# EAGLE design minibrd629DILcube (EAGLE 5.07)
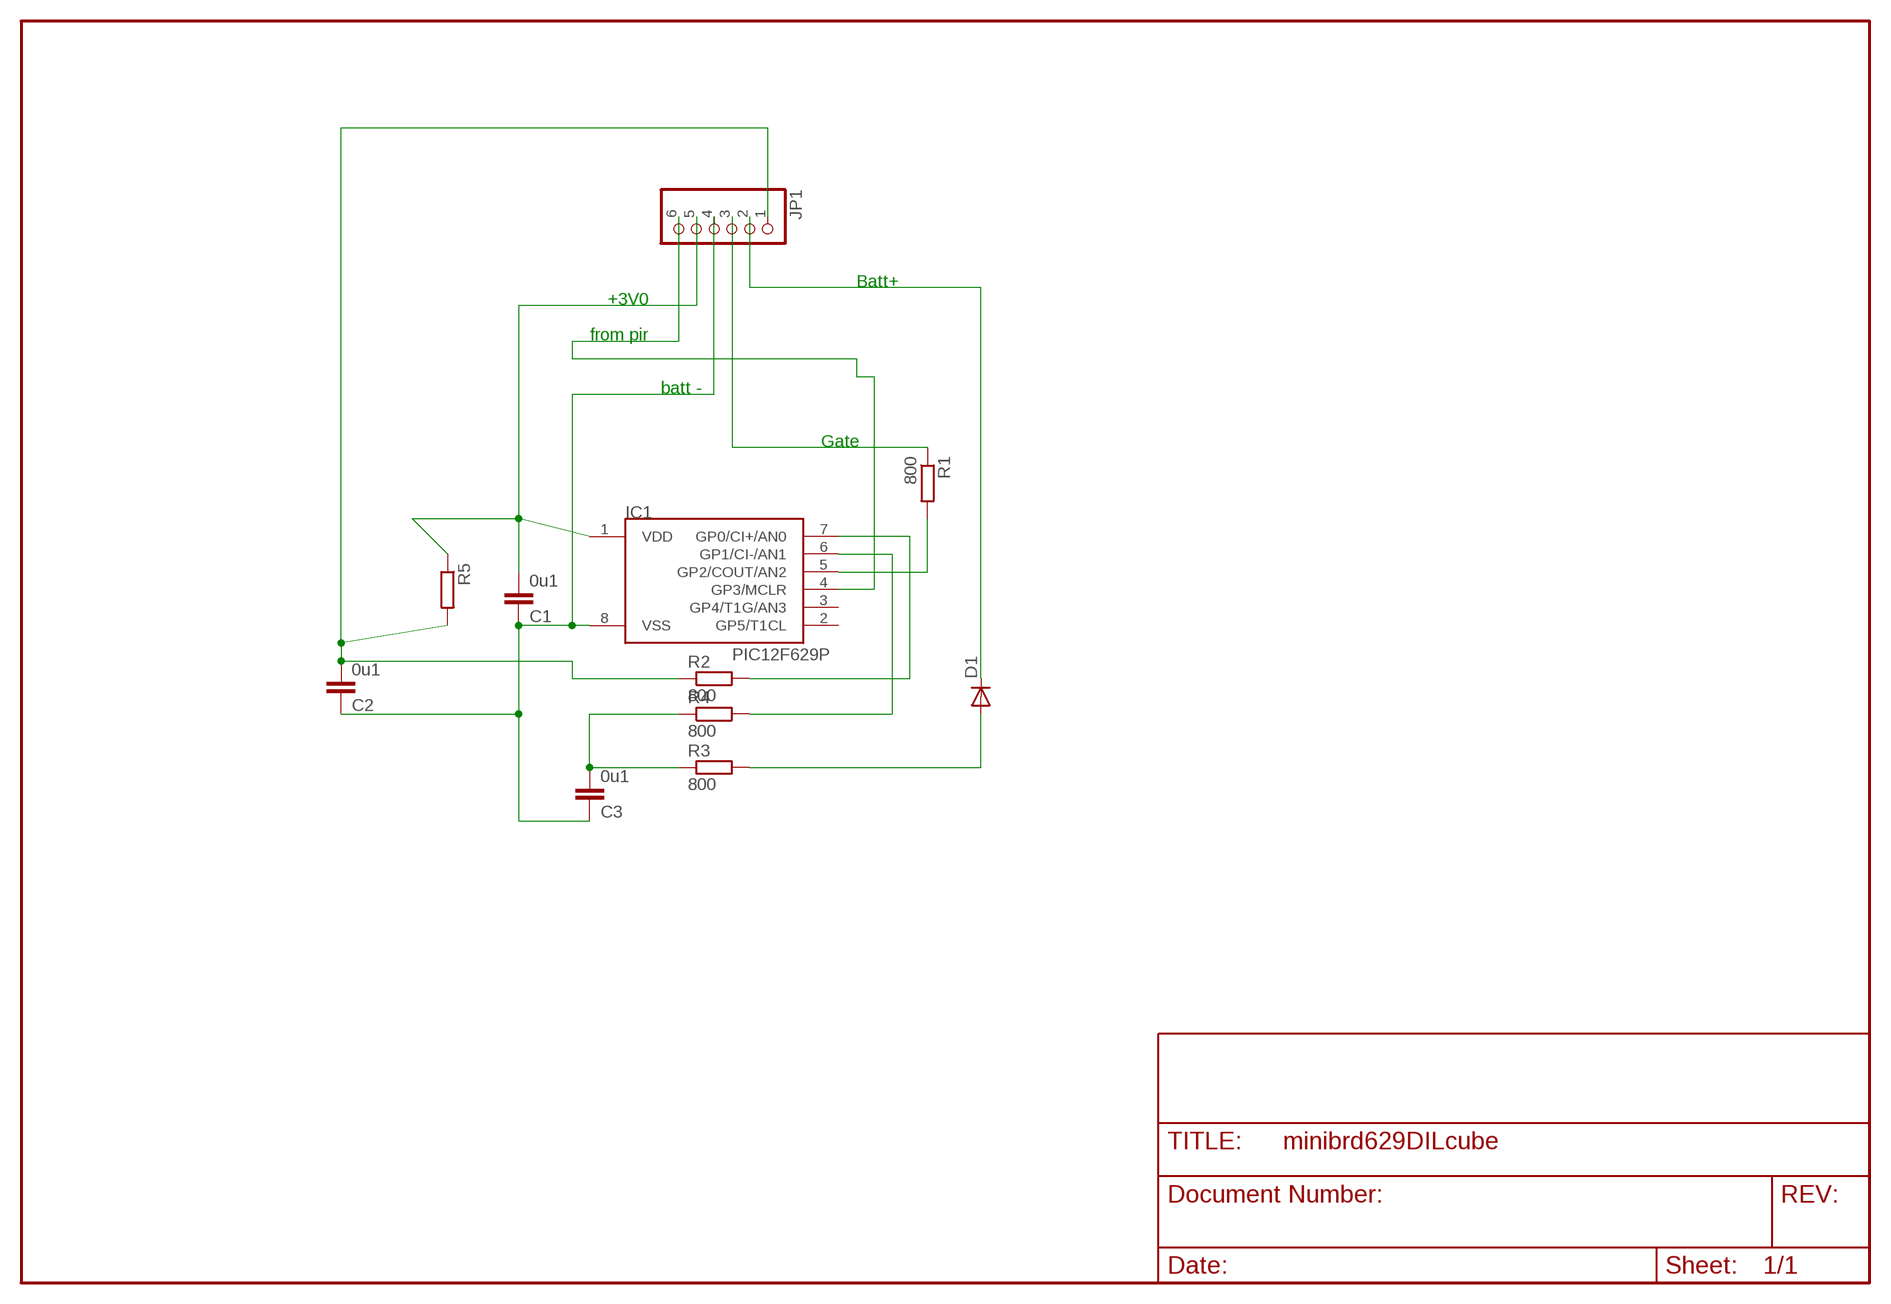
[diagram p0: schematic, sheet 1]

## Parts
C1  0u1  C-EUC1206  [C1206]
C2  0u1  C-EUC1206  [C1206]
C3  0u1  C-EUC1206  [C1206]
D1  DIODE-MINIMELF  [MINIMELF]
IC1  PIC12F629P  [DIL8]
JP1  PINHD-1X6  [1X06BOX]
R1  800  R-EU_R1206  [R1206]
R2  800  R-EU_R1206  [R1206]
R3  800  R-EU_R1206  [R1206]
R4  800  R-EU_R1206  [R1206]
R5  R-EU_0613/5V  [P0613V]

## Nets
GATE: JP1.3 R1.1
N$1: IC1.5(GP2/COUT/AN2) R1.2
N$4: IC1.7(GP0/CI+/AN0) R2.2
N$7: C3.2 R3.1 R4.1
N$8: IC1.6(GP1/CI-/AN1) R4.2
N$9: C2.2 JP1.1 R2.1 R5.2
N$10: D1.A R3.2
PIR: IC1.4(GP3/MCLR) JP1.6
V3: C1.2 IC1.1(VDD) JP1.5 R5.1
V+: D1.C JP1.2
V-: C1.1 C2.1 C3.1 IC1.8(VSS) JP1.4
Unconnected: IC1.2(GP5/T1CL) IC1.3(GP4/T1G/AN3)

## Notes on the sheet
- Batt+
- +3V0
- from pir
- batt -
- Gate

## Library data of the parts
C1-C3 = rcl:C-EU: CAPACITOR, European symbol
D1 = diode-1:DIODE-: DIODE
IC1 = microchip-3:PIC12F6*: uPC nW 1k Program Flash memory 2x Timer Comparator 10b A/D converter/ 4xIN
JP1 = pinhead:PINHD-1X6: PIN HEADER
R1-R5 = rcl:R-EU_: RESISTOR, European symbol

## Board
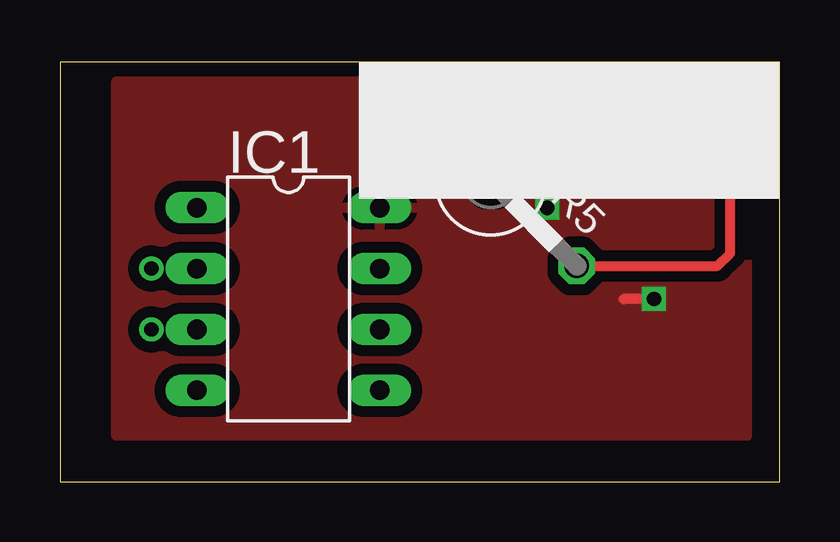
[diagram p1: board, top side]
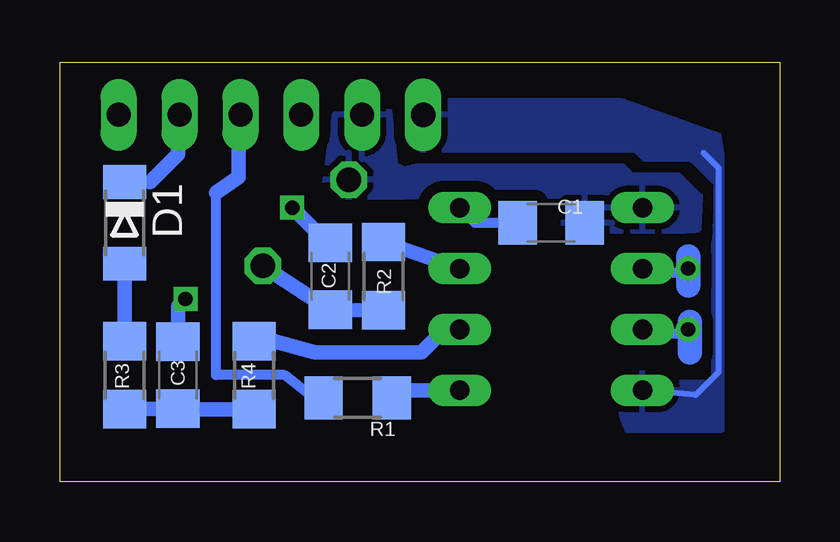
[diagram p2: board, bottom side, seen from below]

Size 30 x 17.5 mm. Coordinates in mm from the lower left corner, seen from the top.
Outline: 0,0 30,0 30,17.5 0,17.5 0,0
Copper layers (1*16): Top 0.035mm / dielectric 1.5mm / Bottom 0.035mm
Design rules "default *": minimum track width 10mil, minimum drill 24mil, track to track 18mil, track to pad 12mil, pad to pad 8mil, via to via 8mil, smd to smd 8mil, copper to edge 1mil, drill to drill 8mil, minimum pad ring 10mil, minimum via ring 8mil, stop-mask expansion 4mil, vias tented up to drill 0mil, thermal gap 10mil

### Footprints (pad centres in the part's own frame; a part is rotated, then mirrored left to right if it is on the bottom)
C1206 = smd 1.6 x 1.8: 1 -1.4,0; 2 1.4,0
MINIMELF = smd 1.4 x 1.8: A 1.7,0; C -1.7,0
DIL8 = drill 0.813 long: 1 -3.81,-3.81; 2 -1.27,-3.81; 3 1.27,-3.81; 4 3.81,-3.81; 5 3.81,3.81; 6 1.27,3.81; 7 -1.27,3.81; 8 -3.81,3.81
1X06BOX = drill 1 long: 1 -6.35,0; 2 -3.81,0; 3 -1.27,0; 4 1.27,0; 5 3.81,0 | drill 1.016 long: 6 6.35,0
R1206 = smd 1.6 x 1.803: 1 -1.422,0; 2 1.422,0
P0613V = drill 1.016 octagon: 1 -2.54,0; 2 2.54,0

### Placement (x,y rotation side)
C1  9.53,10.79 0 bottom
C2  18.73,8.57 270 bottom
C3  25.08,4.45 270 bottom
D1  27.3,10.79 270 bottom
IC1  9.53,7.62 270 top
JP1  21.21,15.3 180 top
R1  17.59,3.49 0 bottom
R2  16.51,8.57 90 bottom
R3  27.3,4.45 90 bottom
R4  21.91,4.45 90 bottom
R5  19.75,10.79 315 top

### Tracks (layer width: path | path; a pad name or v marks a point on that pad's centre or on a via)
GATE
  Bottom 0.406: R1.1 19.05,3.17 20.64,4.45 23.5,4.45 23.5,12.06 | 22.54,15.05 JP1.3
  Bottom 0.61: 23.5,12.06 22.54,12.7 22.54,15.05
N$1
  Bottom 0.406: 15.56,3.81 R1.2
  Bottom 0.61: IC1.5 15.56,3.81
N$2  (via drill 0.6)
  other vias: 3.81,6.35
N$3  (via drill 0.6)
  other vias: 3.81,8.89
N$4
  Bottom 0.61: IC1.7 R2.2
N$5
  Bottom 0.406: 5.78,6.16 3.75,6.16 3.75,6.29
  Bottom 1.016: 3.75,5.4 3.75,6.29 3.75,6.67
N$6
  Bottom 0.406: 5.71,8.76 5.71,8.7 3.81,8.7 3.81,8.64
  Bottom 1.016: 3.81,8.19 3.81,8.64 3.81,9.4
N$7
  Bottom 0.406: 25.06,3.02 C3.2 | 27.28,3.04 R3.1
  Bottom 0.61: R4.1 25.06,3.02 | C3.2 27.28,3.04
N$8
  Bottom 0.406: 21.11,5.87 R4.2 | IC1.6 13.97,6.35
  Bottom 0.61: 21.11,5.87 19.37,5.4 14.92,5.4 13.97,6.35
N$9
  Top 0.406: R5.2 27.41,9 27.94,9.53 27.94,14.92 JP1.1
  Bottom 0.61: R2.1 C2.2 R5.2
N$10
  Bottom 0.61: R3.2 D1.A
PIR
  Bottom 0.254: IC1.4 3.49,3.62 2.54,4.57 2.54,13.08 3.17,13.72
  pour Bottom (isolate 0.406, rank 2): 4.25,4.51 6.03,4.51 6.6,3.94 6.6,2.79 6.35,2.16 2.41,2.16 2.41,13.65 2.54,14.41 6.6,15.88 15.49,15.88 15.56,13.91 14.16,13.65 9.4,13.4 4.32,13.4 2.73,12.19 2.73,4.25 2.98,4.13 4.25,4.13 4.45,4.32
V3
  pour Bottom (isolate 0.406): 3.62,10.48 3.37,10.54 3.3,11.87 4.19,12.76 6.16,12.76 6.54,13.14 15.11,13.14 15.62,13.02 16,13.21 16.26,15.43 18.54,15.3 19.05,11.87 9.02,11.94 9.02,10.48
V+
  Bottom 0.406: D1.C 26.24,12.49 | 25.08,15.24 JP1.2
  Bottom 0.61: 26.24,12.49 25.08,13.65 25.08,15.24
V-  (via drill 0.6)
  Top 0.406: v24.77,7.62 23.5,7.62 | v20.32,11.43 20.32,12.7
  Bottom 0.406: C2.1 18.71,9.82 | C1.1 12.7,10.79 IC1.8
  Bottom 0.61: C3.1 25.08,7.3 v24.77,7.62 | 18.71,9.82 v20.32,11.43
  pour Top (isolate 0.406): 2.35,16.7 28.64,16.7 28.64,1.91 2.35,1.91 2.35,6.41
